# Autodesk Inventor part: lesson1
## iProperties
Author: Administrator
Revision Number: A
Created: 2001-08
Part Number: lesson1
Document SubType Name: Modeling
Designer: Elise Moss
Project: Inventor Textbook
Description: Bracket
Control State: 0
Master: False
Checked Out: False
PropertySet Name: Design Tracking Control
Length Units: 11272
Angle Units: 11279
Time Units: 11290
Mass Units: 11286
Shininess: 3
Angle Display Precision: 2
Document Length Units: 11272
Document Angle Units: 11286
Document Time Units: 11279
Document Mass Units: 11290
Document Length Units Precision: 3
Document Angle Units Precision: 2
Compacted: False
PropertySet Name: _Private Model Information
Density: 0.0
Volumn: 0.0
Area: 0.0
PropertySet Name: Model Information
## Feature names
1. Extrusion1
